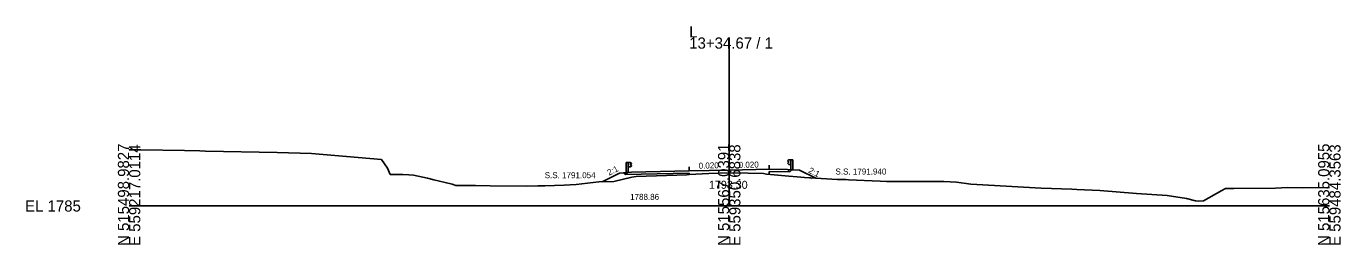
# Model space of a CAD drawing. Extents: x -26 to 1303, y -10 to 9545.
# Drawn here: x -25.7 to 302.8, y 9490.3 to 9544.9 of the extents above; entities that cross this region are included whole.
import ezdxf

# ---------------------------------------------------------------- set-up
doc = ezdxf.new("R2010")
doc.units = 0
for name, color, linetype in [('Exist Cross Section Cell', 7, 'Continuous'), ('Exist XS Center Line Elevation Label', 7, 'Continuous'), ('Exist XS Ground Line', 7, 'Continuous'), ('Prop XS Ditch Slope Text', 7, 'Continuous'), ('Prop XS Ditch Standard Text', 7, 'Continuous'), ('Prop XS Dump Level', 7, 'Continuous'), ('Prop XS EOT Tick Mark', 7, 'Continuous'), ('Prop XS Finish Grade', 7, 'Continuous'), ('Prop XS Finish Grade Earthwork', 7, 'Continuous'), ('Prop XS Finish Grade Paved Shoulder', 7, 'Continuous'), ('Prop XS Finish Grade Pavement', 7, 'Continuous'), ('Prop XS Guardrail', 7, 'Continuous'), ('Prop XS Pvmt Edge Slope', 7, 'Continuous'), ('Prop XS SE Text', 7, 'Continuous'), ('Prop XS SS Elevation Text', 7, 'Continuous'), ('Prop XS Subgrade Earthwork', 7, 'Continuous')]:
    doc.layers.add(name, color=color, linetype=linetype)

msp = doc.modelspace()

# ---------------------------------------------------------------- linework, layer by layer
at = {"layer": 'Exist Cross Section Cell'}
for p, q in [((150, 9500), (150, 9542.14)), ((0, 9500), (150, 9500)), ((150, 9500), (300, 9500))]:
    msp.add_line(p, q, dxfattribs=at)
at = {"layer": 'Exist XS Ground Line'}
for p, q in [((0, 9514), (2.95, 9514.05)), ((2.95, 9514.05), (13.82, 9513.83)), ((13.82, 9513.83), (17.65, 9513.77)), ((17.65, 9513.77), (19.07, 9513.73)), ((19.07, 9513.73), (37.02, 9513.41)), ((37.02, 9513.41), (45.61, 9513.12)), ((45.61, 9513.12), (63.1, 9511.6)), ((63.1, 9511.6), (64.57, 9509.43)), ((64.57, 9509.43), (65.24, 9507.9)), ((65.24, 9507.9), (68.42, 9507.86)), ((68.42, 9507.86), (69.89, 9507.81)), ((69.89, 9507.81), (71.13, 9507.69)), ((126.77, 9507.38), (139.42, 9507.81)), ((139.42, 9507.81), (140.01, 9507.83)), ((140.01, 9507.83), (144.93, 9508.08)), ((144.93, 9508.08), (150.04, 9508.3)), ((150.04, 9508.3), (154.7, 9508.18)), ((154.7, 9508.18), (158.53, 9508.1)), ((158.53, 9508.1), (159.33, 9507.94)), ((159.33, 9507.94), (161.26, 9507.82)), ((161.26, 9507.82), (164.87, 9507.48)), ((71.13, 9507.69), (74.62, 9506.92)), ((74.62, 9506.92), (76.15, 9506.56)), ((76.15, 9506.56), (78.98, 9505.85)), ((78.98, 9505.85), (80.78, 9505.45)), ((80.78, 9505.45), (81.71, 9505.15)), ((81.71, 9505.15), (86.57, 9505.1)), ((86.57, 9505.1), (90.25, 9505.06)), ((90.25, 9505.06), (99.31, 9504.97)), ((99.31, 9504.97), (102.2, 9505)), ((102.2, 9505), (103.88, 9505.06)), ((103.88, 9505.06), (108.72, 9505.22)), ((108.72, 9505.22), (111.73, 9505.37)), ((111.73, 9505.37), (117.45, 9506.03)), ((117.45, 9506.03), (121.18, 9506.15)), ((121.18, 9506.15), (125.66, 9507.18)), ((125.66, 9507.18), (126.77, 9507.38)), ((164.87, 9507.48), (166.96, 9507.32)), ((166.96, 9507.32), (168.8, 9507.16)), ((168.8, 9507.16), (170.33, 9507.01)), ((170.33, 9507.01), (176.95, 9506.66)), ((176.95, 9506.66), (177.85, 9506.66)), ((177.85, 9506.66), (178.39, 9506.61)), ((178.39, 9506.61), (179.13, 9506.58)), ((179.13, 9506.58), (179.84, 9506.57)), ((179.84, 9506.57), (187.76, 9506.17)), ((187.76, 9506.17), (189.34, 9506.12)), ((189.34, 9506.12), (199.82, 9506.1)), ((199.82, 9506.1), (203.63, 9506.14)), ((203.63, 9506.14), (206.79, 9505.93)), ((206.79, 9505.93), (210.4, 9505.46)), ((210.4, 9505.46), (211.87, 9505.33)), ((211.87, 9505.33), (227.96, 9504.47)), ((227.96, 9504.47), (235.63, 9504.17)), ((286.57, 9504.41), (289.51, 9504.6)), ((289.51, 9504.6), (293.31, 9504.53)), ((293.31, 9504.53), (300, 9504.62)), ((235.63, 9504.17), (236.86, 9504.11)), ((236.86, 9504.11), (242.64, 9503.89)), ((242.64, 9503.89), (251.76, 9503.15)), ((251.76, 9503.15), (259.47, 9502.59)), ((259.47, 9502.59), (264.26, 9501.86)), ((264.26, 9501.86), (266.52, 9501.27)), ((266.52, 9501.27), (267.18, 9501.21)), ((267.18, 9501.21), (268.52, 9501.27)), ((268.52, 9501.27), (273.11, 9503.88)), ((273.11, 9503.88), (274.07, 9504.34)), ((274.07, 9504.34), (274.7, 9504.36)), ((274.7, 9504.36), (276.15, 9504.38)), ((276.15, 9504.38), (286.57, 9504.41))]:
    msp.add_line(p, q, dxfattribs=at)
at = {"layer": 'Prop XS Dump Level'}
for p, q in [((140, 9508.77), (150, 9508.97)), ((150, 9508.97), (160, 9509.17))]:
    msp.add_line(p, q, dxfattribs=at)
at = {"layer": 'Prop XS EOT Tick Mark'}
for p, q in [((140, 9508.77), (140, 9509.77)), ((160, 9509.17), (160, 9510.17))]:
    msp.add_line(p, q, dxfattribs=at)
at = {"layer": 'Prop XS Finish Grade'}
for p, q in [((125.6, 9508.48), (124.58, 9508.4)), ((164.6, 9509.08), (165.62, 9509.04))]:
    msp.add_line(p, q, dxfattribs=at)
at = {"layer": 'Prop XS Finish Grade Earthwork'}
for p, q in [((122.6, 9508.24), (118.22, 9506.05)), ((124.58, 9508.4), (122.6, 9508.24)), ((165.62, 9509.04), (167.6, 9508.95)), ((167.6, 9508.95), (171.62, 9506.94))]:
    msp.add_line(p, q, dxfattribs=at)
at = {"layer": 'Prop XS Finish Grade Paved Shoulder'}
for p, q in [((140, 9508.77), (125.6, 9508.48)), ((160, 9509.17), (164.6, 9509.08))]:
    msp.add_line(p, q, dxfattribs=at)
at = {"layer": 'Prop XS Finish Grade Pavement'}
for p, q in [((140, 9508.77), (150, 9508.97)), ((150, 9508.97), (160, 9509.17))]:
    msp.add_line(p, q, dxfattribs=at)
at = {"layer": 'Prop XS Guardrail'}
for p, q in [((164.63, 9511.35), (164.6, 9511.29)), ((164.6, 9511.29), (164.63, 9511.23)), ((164.92, 9511.55), (164.63, 9511.35)), ((164.63, 9511.23), (164.92, 9511.03)), ((165.42, 9511.55), (164.92, 9511.55)), ((164.92, 9511.03), (164.92, 9510.93)), ((165.92, 9511.55), (165.42, 9511.55)), ((165.42, 9511.55), (165.42, 9509.05)), ((165.92, 9509.02), (165.92, 9511.55)), ((124.28, 9510.91), (124.78, 9510.91)), ((124.28, 9508.36), (124.28, 9510.91)), ((124.78, 9510.91), (125.28, 9510.91)), ((124.78, 9510.91), (124.78, 9508.41)), ((125.28, 9509.77), (124.78, 9509.77)), ((125.28, 9510.91), (125.57, 9510.71)), ((125.57, 9510.59), (125.28, 9510.39)), ((125.28, 9510.39), (125.28, 9510.29)), ((125.28, 9510.29), (125.57, 9510.09)), ((125.57, 9509.97), (125.28, 9509.77)), ((125.57, 9510.71), (125.6, 9510.65)), ((125.6, 9510.65), (125.57, 9510.59)), ((125.57, 9510.09), (125.6, 9510.03)), ((125.6, 9510.03), (125.57, 9509.97)), ((164.63, 9510.73), (164.6, 9510.67)), ((164.6, 9510.67), (164.63, 9510.61)), ((164.92, 9510.93), (164.63, 9510.73)), ((164.63, 9510.61), (164.92, 9510.41)), ((164.92, 9510.41), (165.42, 9510.41))]:
    msp.add_line(p, q, dxfattribs=at)
at = {"layer": 'Prop XS Pvmt Edge Slope'}
for p, q in [((124.58, 9508.4), (124.02, 9507.85)), ((164.6, 9509.08), (165.13, 9508.55))]:
    msp.add_line(p, q, dxfattribs=at)
at = {"layer": 'Prop XS Subgrade Earthwork'}
for p, q in [((124.02, 9507.85), (123.55, 9508.32)), ((140, 9508.23), (124.02, 9507.85)), ((140, 9508.23), (140, 9507.83)), ((160, 9508.63), (160, 9507.9)), ((160, 9508.63), (165.13, 9508.55)), ((165.13, 9508.55), (165.62, 9509.04))]:
    msp.add_line(p, q, dxfattribs=at)

# ---------------------------------------------------------------- texts
at = {"layer": 'Exist Cross Section Cell'}
for s, p in [('L', (140, 9542.14)), ('13+34.67 / 1', (140, 9539.34)), ('EL 1785', (-26, 9498.6))]:
    msp.add_text(s, height=2.8, dxfattribs=at).set_placement(p)
for s, p in [('N 515498.9827', (0, 9490)), ('E 559217.0114', (2.8, 9490)), ('N 515567.0391', (150, 9490)), ('E 559350.6838', (152.8, 9490)), ('N 515635.0955', (300, 9490)), ('E 559484.3563', (302.8, 9490))]:
    msp.add_text(s, height=2.8, rotation=90, dxfattribs=at).set_placement(p)
at = {"layer": 'Exist XS Center Line Elevation Label'}
msp.add_text('1793.30', height=2, dxfattribs=at).set_placement((144.94, 9504.3))
at = {"layer": 'Prop XS Ditch Slope Text'}
for rotation, p in [(26.5651, (119.97, 9507.56)), (333.4349, (169.66, 9508.4))]:
    msp.add_text('2:1', height=1.5, rotation=rotation, dxfattribs=at).set_placement(p)
at = {"layer": 'Prop XS Ditch Standard Text'}
msp.add_text('1788.86', height=1.5, dxfattribs=at).set_placement((125.23, 9501.53))
at = {"layer": 'Prop XS Dump Level'}
for s, height, p in [('Case1', 0.04, (163, 9509.01)), ('Eop', 0.3, (170, 9506.74))]:
    msp.add_text(s, height=height, dxfattribs=at).set_placement(p)
at = {"layer": 'Prop XS SE Text'}
for p in [(152.38, 9509.52), (142.38, 9509.32)]:
    msp.add_text('0.020', height=1.5, rotation=1.1458, dxfattribs=at).set_placement(p)
at = {"layer": 'Prop XS SS Elevation Text'}
for s, p in [('S.S. 1791.054', (103.88, 9506.95)), ('S.S. 1791.940', (176.56, 9507.86))]:
    msp.add_text(s, height=1.5, dxfattribs=at).set_placement(p)

doc.saveas('drawing.dxf')
